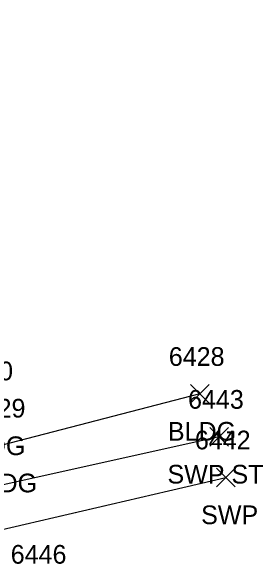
# Model space of a CAD drawing. Extents: x 1769141 to 1770817, y 735471 to 742405.
# Drawn here: x 1770299 to 1770325.9, y 740788.4 to 740847.6 of the extents above; entities that cross this region are included whole.
import ezdxf

# ---------------------------------------------------------------- set-up
doc = ezdxf.new("R2010")
doc.units = 0
for name, color, linetype in [('L_A', 7, 'Continuous'), ('L_I', 7, 'Continuous'), ('L_TIC', 7, 'Continuous'), ('LBC', 7, 'Continuous'), ('R_A', 7, 'Continuous'), ('R_I', 7, 'Continuous'), ('R_TIC', 7, 'Continuous'), ('RSW', 7, 'Continuous'), ('U_I', 7, 'Continuous')]:
    doc.layers.add(name, color=color, linetype=linetype)

msp = doc.modelspace()

# ---------------------------------------------------------------- linework, layer by layer
at = {"layer": 'L_TIC'}
for points in [[(1770318.128, 740805.628), (1770320.128, 740807.628)], [(1770320.128, 740805.628), (1770318.128, 740807.628)]]:
    msp.add_lwpolyline(points, dxfattribs=at)
at = {"layer": 'LBC'}
msp.add_lwpolyline([(1770319.128, 740806.628), (1770297.879, 740801.102), (1770296.632, 740805.083), (1770293.266, 740806.948), (1770292.047, 740811.448), (1770294.139, 740814.916), (1770293.756, 740817.035), (1770290.358, 740830.172), (1770289.843, 740831.832), (1770286.419, 740833.621), (1770285.236, 740838.24), (1770287.378, 740841.622), (1770286.406, 740845.581), (1770294.231, 740847.568)], dxfattribs=at)
at = {"layer": 'R_TIC'}
for points in [[(1770320.183, 740801.043), (1770322.183, 740803.043)], [(1770322.183, 740801.043), (1770320.183, 740803.043)], [(1770320.91, 740796.7), (1770322.91, 740798.7)], [(1770322.91, 740796.7), (1770320.91, 740798.7)]]:
    msp.add_lwpolyline(points, dxfattribs=at)
at = {"layer": 'RSW'}
for points in [[(1770321.183, 740802.043), (1770294.122, 740796.011), (1770292.512, 740799.787)], [(1770289.158, 740799.18), (1770291.252, 740790.547), (1770321.91, 740797.7)]]:
    msp.add_lwpolyline(points, dxfattribs=at)

# ---------------------------------------------------------------- texts
at = {"layer": 'L_A'}
for p in [(1770315.719, 740801.628), (1770293.222, 740800.083), (1770294.47, 740796.102)]:
    msp.add_text('BLDG', height=2, dxfattribs=at).set_placement(p)
at = {"layer": 'L_I'}
for s, p in [('6428', (1770315.821, 740809.628)), ('6430', (1770293.238, 740808.083)), ('6429', (1770294.564, 740804.102))]:
    msp.add_text(s, height=2, dxfattribs=at).set_placement(p)
at = {"layer": 'R_A'}
for s, p in [('SWP ST', (1770315.679, 740797.043)), ('SWP', (1770319.272, 740792.7))]:
    msp.add_text(s, height=2, dxfattribs=at).set_placement(p)
at = {"layer": 'R_I'}
for s, p in [('6443', (1770317.876, 740805.043)), ('6442', (1770318.603, 740800.7))]:
    msp.add_text(s, height=2, dxfattribs=at).set_placement(p)
at = {"layer": 'U_I'}
msp.add_text('6446', height=2, dxfattribs=at).set_placement((1770298.941, 740788.475))

doc.saveas('drawing.dxf')
